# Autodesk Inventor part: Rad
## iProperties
Created: 2003-04
Part Number: Rad
Material: Kunststoff
Document SubType Name: Modellieren
Designer: Administrator
Control State: 0
Master: False
Checked Out: False
Shininess: 20.0
Angle Display Precision: 2
Document Length Units: 11269
Document Angle Units: 11279
Document Time Units: 11290
Document Mass Units: 11283
Document Length Units Precision: 3
Document Angle Units Precision: 2
Density: 0.0
Volumn: 0.0
Area: 0.0
PropertySet Name: Model Information
Author: Administrator
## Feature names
1. Drehung1 [Revolution]
2. Rundung1 [Fillet]
